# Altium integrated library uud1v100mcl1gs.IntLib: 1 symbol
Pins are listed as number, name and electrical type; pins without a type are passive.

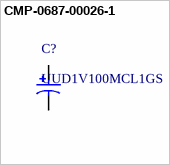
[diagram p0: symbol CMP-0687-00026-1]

## CMP-0687-00026-1
designator C?, comment UUD1V100MCL1GS
Aluminum Electrolytic Capacitor, UD Series, Low Impedance, 10 uF, 35 V, + / - 20%, -55 to 105 degC, Chip Type, 5 x 5.8 mm D x L, Pb-Free, Reel; Manufacturer: Nichicon; Endurance Time: 2000 h; Tolerance Rated Capacitance: -20 to 20%; Packing: Dia382mm Reel; Rated Capacitance: 10 uF; Rated Ripple Current (at 100kHz): 150 mA; Impedance: 0.76 Ohm; Rated Voltage: 35 V
footprint NIC-CAPA2-5X5.8_V (Aluminum Electrolytic Capacitor, Diameter 5mm, Height 6.1mm, Pitch 4.4mm)
pins: 1, 2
